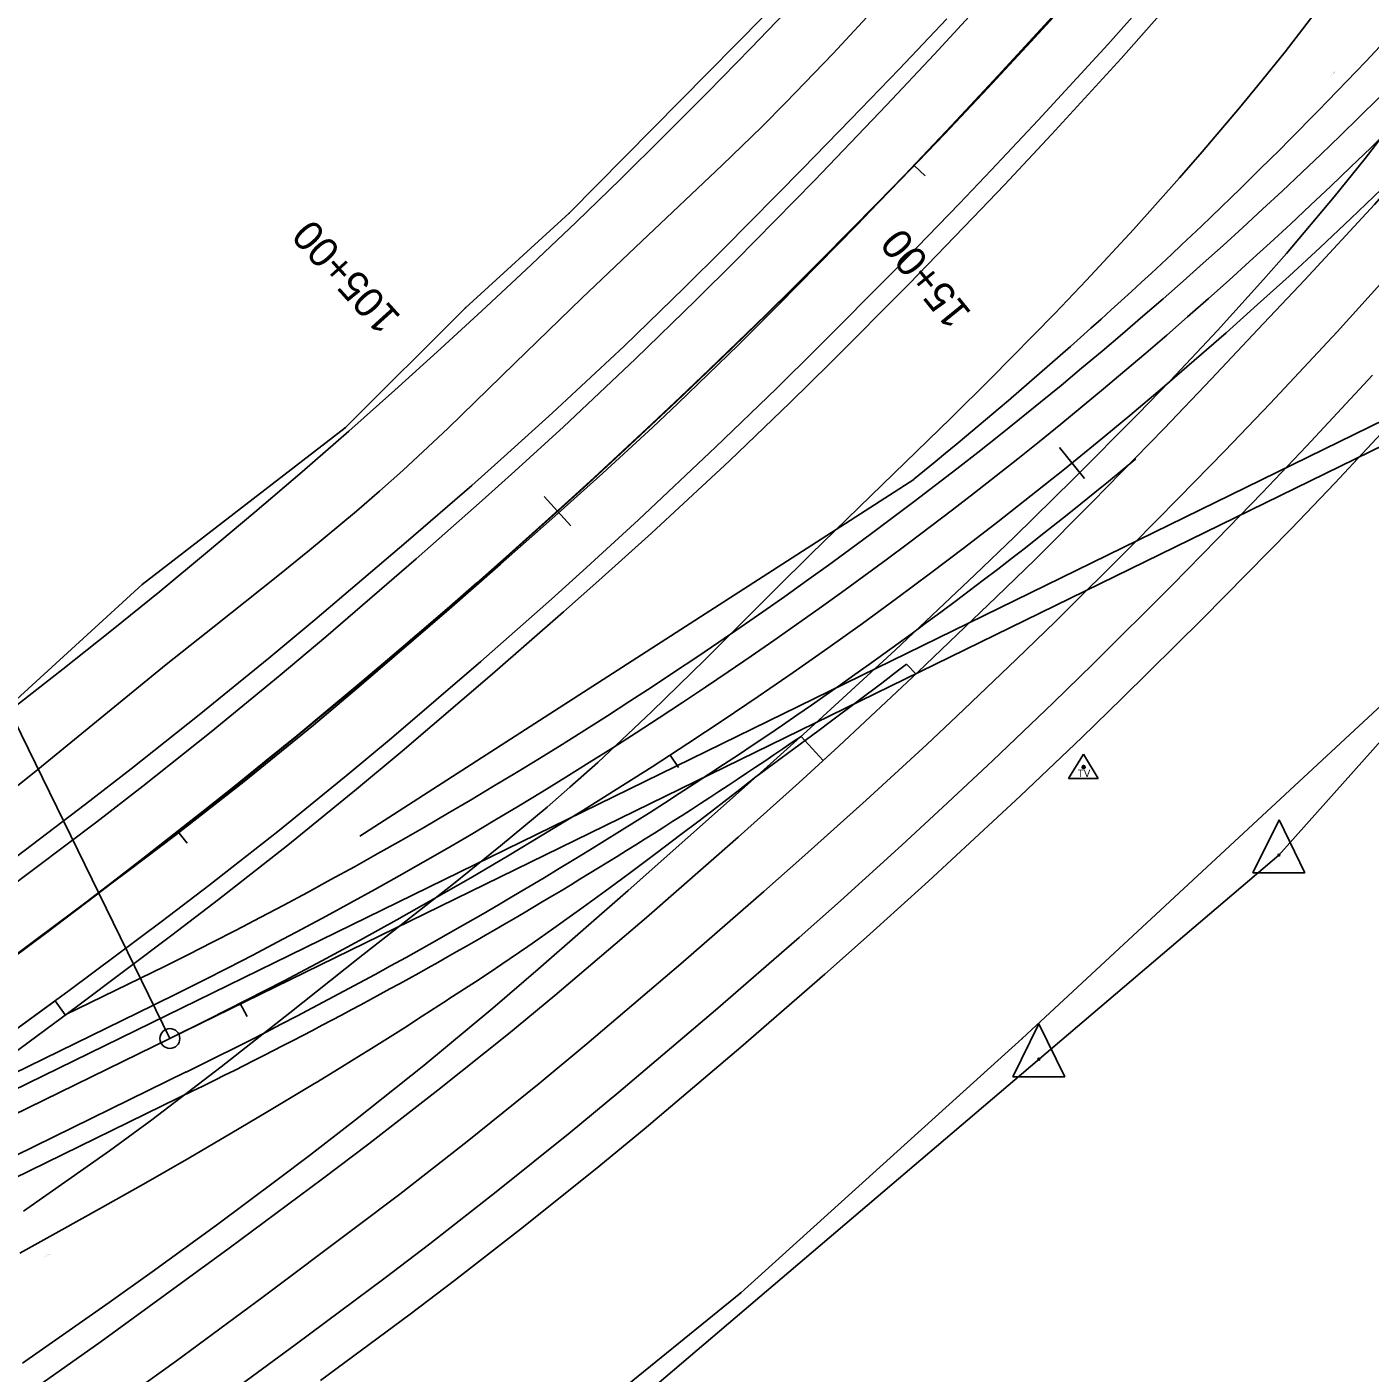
# Model space of a CAD drawing. Extents: x 1674300 to 1677920, y 225056 to 231852.
# Drawn here: x 1676793.2 to 1677063.6, y 227740.3 to 228011.3 of the extents above; entities that cross this region are included whole.
import ezdxf

# ---------------------------------------------------------------- set-up
doc = ezdxf.new("R2010")
doc.units = 0
for name, color, linetype in [('R_Annotation', 7, 'Continuous'), ('R_Horz Alg', 7, 'Continuous'), ('R_Horz Alg Annot', 7, 'Continuous'), ('R_Proposed Const Limits_Fill', 7, 'Continuous'), ('R_Proposed Road_Lane', 7, 'Continuous'), ('R_Proposed Road_Shoulder', 7, 'Continuous'), ('S_DITCHLINE', 7, 'Continuous'), ('S_EDGE_PAVEMENT', 7, 'Continuous'), ('S_EXIST_ROW', 7, 'Continuous'), ('S_EXISTING_ALIGNMENT', 7, 'Continuous'), ('S_FIBER_OPTIC_CABLE', 7, 'Continuous'), ('S_PAVEMENT_CROWN', 7, 'Continuous'), ('S_SECONDARY_CTL', 7, 'Continuous'), ('S_SHOULDER', 7, 'Continuous'), ('S_UTL_PT_SYM', 7, 'Continuous')]:
    doc.layers.add(name, color=color, linetype=linetype)

msp = doc.modelspace()

# ---------------------------------------------------------------- linework, layer by layer
at = {"layer": 'R_Horz Alg'}
msp.add_line((1676566.75, 227682.84), (1676822.03, 227807.69), dxfattribs=at)
for centre, radius, end in [((1675928.16, 228988.54), 1449, 0.80558), ((1676402.48, 228665.51), 954.93, 328.88259)]:
    msp.add_arc(centre, radius, 296.0624, end, dxfattribs=at)
at = {"layer": 'R_Horz Alg Annot'}
for p, q in [((1676564.78, 227686.88), (1677389.93, 228090.45)), ((1676822.03, 227807.69), (1677074.66, 227931.25))]:
    msp.add_line(p, q, dxfattribs=at)
for points in [[(1676974.02, 227981.32), (1676971.86, 227983.41)], [(1677001.08, 227926.63), (1677006.11, 227920.42)], [(1676822.03, 227807.69), (1676769.3, 227915.48)], [(1676897.38, 227916.79), (1676902.74, 227910.86)], [(1676924.38, 227862.24), (1676922.74, 227864.75)], [(1676825.49, 227847.01), (1676823.64, 227849.36)], [(1676837.55, 227812.09), (1676836.19, 227814.76)]]:
    msp.add_lwpolyline(points, dxfattribs=at)
msp.add_circle((1676822.03, 227807.69), 2, dxfattribs=at)
at = {"layer": 'R_Proposed Const Limits_Fill'}
msp.add_line((1676970.31, 227883.06), (1676972.23, 227881.05), dxfattribs=at)
for points in [[(1676860.25, 227848.42), (1676971.76, 227920.24)], [(1676791.82, 227764.49), (1676799.7, 227768.86), (1676808.45, 227773.71), (1676817.16, 227778.65), (1676825.85, 227783.62), (1676834.5, 227788.69), (1676841.39, 227792.77), (1676843.11, 227793.8), (1676851.16, 227798.64), (1676851.72, 227798.97), (1676856.62, 227801.97), (1676860.5, 227804.37), (1676862.05, 227805.32), (1676867.46, 227808.7), (1676869.23, 227809.82), (1676872.83, 227812.15), (1676877.85, 227815.42), (1676878.17, 227815.64), (1676883.52, 227819.1), (1676886.46, 227821.03), (1676888.82, 227822.64), (1676894.08, 227826.23), (1676894.95, 227826.82), (1676899.3, 227829.88), (1676903.32, 227832.77), (1676904.47, 227833.6), (1676909.62, 227837.34), (1676911.62, 227838.8), (1676914.76, 227841.08), (1676919.83, 227844.91), (1676919.84, 227844.92), (1676924.9, 227848.75), (1676928.01, 227851.1), (1676929.95, 227852.58), (1676934.98, 227856.45), (1676936.12, 227857.33), (1676939.99, 227860.33), (1676944.26, 227863.49), (1676945.07, 227864.09), (1676950.14, 227867.87), (1676952.43, 227869.57), (1676955.21, 227871.64), (1676960.26, 227875.42), (1676960.59, 227875.66), (1676965.3, 227879.22), (1676968.69, 227881.82), (1676970.31, 227883.06)]]:
    msp.add_lwpolyline(points, dxfattribs=at)
msp.add_arc((1676364.65, 228668.23), 963.36, 309.06481, 319.55161, dxfattribs=at)
at = {"layer": 'R_Proposed Road_Lane'}
for p, q in [((1676748.93, 227780.28), (1676818.73, 227814.42)), ((1676570.05, 227676.1), (1676825.32, 227800.95))]:
    msp.add_line(p, q, dxfattribs=at)
for points in [[(1676953.5, 227863.64), (1676956.64, 227866.52), (1676972.6, 227881.4), (1676988.37, 227896.5), (1676996.17, 227904.12), (1677007.75, 227915.68), (1677022.13, 227930.45), (1677031.62, 227940.39), (1677041.04, 227950.41), (1677050.47, 227960.42), (1677064.47, 227975.57), (1677071.28, 227983.29), (1677077.87, 227991.2), (1677081.05, 227995.24), (1677086, 228001.89), (1677089.18, 228006.41), (1677095.28, 228015.66), (1677102.54, 228027.13)], [(1676602.96, 227693.74), (1676603.67, 227694.1), (1676620.43, 227702.92), (1676631.53, 227708.93), (1676638.9, 227713), (1676653.56, 227721.26), (1676669.8, 227730.7), (1676680.55, 227737.1), (1676691.25, 227743.62), (1676701.94, 227750.13), (1676720.46, 227761.74), (1676729.67, 227767.63), (1676743.4, 227776.59), (1676757.03, 227785.7), (1676763.8, 227790.32), (1676776.54, 227799.18), (1676784.98, 227805.17), (1676798.91, 227815.26)]]:
    msp.add_lwpolyline(points, dxfattribs=at)
for radius, end in [(947.43, 317.63818), (962.43, 309.63823)]:
    msp.add_arc((1676402.48, 228665.51), radius, 296.0624, end, dxfattribs=at)
at = {"layer": 'R_Proposed Road_Shoulder'}
for p, q in [((1676949.06, 227868.5), (1676953.5, 227863.64)), ((1676800.97, 227812.42), (1676816.09, 227819.81)), ((1676800.97, 227812.42), (1676798.91, 227815.26)), ((1676571.81, 227672.51), (1676827.08, 227797.35))]:
    msp.add_line(p, q, dxfattribs=at)
for radius, end in [(941.43, 317.05629), (966.43, 304.44158)]:
    msp.add_arc((1676402.48, 228665.51), radius, 296.0624, end, dxfattribs=at)
at = {"layer": 'S_DITCHLINE'}
for points in [[(1676781.31, 227850.55), (1676794.72, 227861.22), (1676812.4, 227875.73), (1676821.28, 227882.95), (1676830.91, 227890.62), (1676843.77, 227900.81), (1676850.15, 227905.95), (1676859.6, 227913.82), (1676864.24, 227917.84), (1676868.89, 227922.01), (1676878.02, 227930.53), (1676891.46, 227943.62), (1676904.91, 227956.71), (1676917.04, 227968.18), (1676933.22, 227983.46), (1676941.18, 227991.22), (1676946.01, 227996.08), (1676955.51, 228005.96), (1676964.85, 228016)], [(1676792.57, 227772.92), (1676809.85, 227785.11), (1676818.4, 227791.33), (1676832.36, 227801.97), (1676846.14, 227812.86), (1676859.92, 227823.76), (1676879.09, 227838.84), (1676888.6, 227846.47), (1676897.95, 227854.27), (1676902.55, 227858.26), (1676908.13, 227863.25), (1676919.05, 227873.5), (1676929.77, 227883.98), (1676943.92, 227898.11), (1676951.02, 227905.16), (1676963.08, 227916.92), (1676979.21, 227932.56), (1676987.2, 227940.45), (1677000.17, 227953.65), (1677006.55, 227960.36), (1677015.99, 227970.55), (1677025.23, 227980.9), (1677029.79, 227986.13), (1677037.31, 227995.01), (1677041.02, 227999.5), (1677046.49, 228006.3), (1677054.51, 228016.66)]]:
    msp.add_lwpolyline(points, dxfattribs=at)
at = {"layer": 'S_EDGE_PAVEMENT'}
for points in [[(1676784.98, 227805.17), (1676801.74, 227817.32), (1676820.56, 227831.36), (1676829.88, 227838.49), (1676843.73, 227849.37), (1676857.53, 227860.58), (1676866.63, 227868.17), (1676884.63, 227883.6), (1676898.83, 227896.15), (1676905.87, 227902.49), (1676916.35, 227912.09), (1676931.88, 227926.7), (1676944.11, 227938.52), (1676952.18, 227946.48), (1676968.16, 227962.57), (1676980.99, 227975.79), (1676987.34, 227982.45), (1676996.8, 227992.52), (1677010.8, 228007.79), (1677018.43, 228016.32)], [(1676788.62, 227837.24), (1676807.31, 227851.32), (1676816.56, 227858.49), (1676830.31, 227869.4), (1676844.24, 227880.82), (1676853.44, 227888.54), (1676871.63, 227904.22), (1676884.89, 227915.95), (1676891.46, 227921.87), (1676901.25, 227930.84), (1676915.74, 227944.48), (1676927.9, 227956.29), (1676935.92, 227964.26), (1676951.76, 227980.38), (1676966.27, 227995.53), (1676975.83, 228005.73), (1676985.29, 228016.04)], [(1676788.32, 227732.7), (1676795.19, 227737.48), (1676808.2, 227746.7), (1676821.09, 227756.09), (1676833.98, 227765.47), (1676852.77, 227779.44), (1676862.1, 227786.51), (1676875.97, 227797.27), (1676890.15, 227808.64), (1676899.5, 227816.34), (1676917.98, 227832.01), (1676936.44, 227848.2), (1676948.6, 227859.15), (1676956.64, 227866.52), (1676972.6, 227881.4), (1676988.37, 227896.5), (1676996.17, 227904.12), (1677007.75, 227915.68), (1677022.13, 227930.45), (1677031.62, 227940.39), (1677041.04, 227950.41), (1677050.47, 227960.42), (1677064.47, 227975.57)], [(1676829.81, 227733.24), (1676847.27, 227746), (1676865.35, 227759.54), (1676874.33, 227766.39), (1676887.68, 227776.81), (1676902.58, 227788.79), (1676912.41, 227796.9), (1676922.15, 227805.14), (1676931.88, 227813.37), (1676948.66, 227827.99), (1676956.98, 227835.38), (1676969.35, 227846.58), (1676978.52, 227855.1), (1676987.68, 227863.63), (1676999.83, 227875.26), (1677007.86, 227883.09), (1677023.76, 227898.92), (1677032.82, 227908.22), (1677041.88, 227917.51), (1677050.82, 227926.92), (1677064.06, 227941.19)]]:
    msp.add_lwpolyline(points, dxfattribs=at)
at = {"layer": 'S_EXIST_ROW'}
for p, q in [((1677045.25, 227844.61), (1677191.98, 228009.21)), ((1677045.27, 227851.7), (1677039.98, 227841.06)), ((1677045.27, 227851.7), (1677050.5, 227841.06)), ((1676877.29, 227701.73), (1677045.25, 227844.61)), ((1677045.25, 227844.61), (1677045.25, 227844.61)), ((1677039.98, 227841.06), (1677050.5, 227841.06)), ((1676996.96, 227810.61), (1676991.67, 227799.97)), ((1676996.96, 227810.61), (1677002.19, 227799.97)), ((1676996.94, 227803.52), (1676996.94, 227803.52)), ((1676991.67, 227799.97), (1677002.19, 227799.97))]:
    msp.add_line(p, q, dxfattribs=at)
for centre, radius in [((1677045.25, 227844.61), 0.18), ((1677045.25, 227844.61), 0.09), ((1676996.94, 227803.52), 0.18), ((1676996.94, 227803.52), 0.09)]:
    msp.add_circle(centre, radius, dxfattribs=at)
msp.add_arc((1675926.71, 228989.39), 1410.53, 295.94359, 0.85682, dxfattribs=at)
at = {"layer": 'S_EXISTING_ALIGNMENT'}
for start, end in [(315.98862, 345.81316), (295.94359, 315.98862)]:
    msp.add_arc((1675926.71, 228989.39), 1450.53, start, end, dxfattribs=at)
at = {"layer": 'S_FIBER_OPTIC_CABLE'}
for p, q in [((1676902.41, 227973.8), (1676941.57, 228013.45)), ((1676881.55, 227954.79), (1676902.41, 227973.8)), ((1676857.28, 227930.62), (1676881.55, 227954.79)), ((1676816.44, 227899.08), (1676857.28, 227930.62)), ((1676773.26, 227859.62), (1676816.44, 227899.08)), ((1676993.59, 227807.69), (1677078.18, 227886.24)), ((1676936.92, 227756.51), (1676993.59, 227807.69)), ((1676864.37, 227697.61), (1676936.92, 227756.51))]:
    msp.add_line(p, q, dxfattribs=at)
at = {"layer": 'S_PAVEMENT_CROWN'}
for points in [[(1676778.53, 227815.24), (1676795.14, 227827.6), (1676813.86, 227841.57), (1676823.17, 227848.63), (1676836.98, 227859.39), (1676850.91, 227870.74), (1676860.08, 227878.46), (1676878.25, 227894.1), (1676888.59, 227903.18), (1676898.92, 227912.26), (1676909.14, 227921.46), (1676919.24, 227930.77), (1676924.24, 227935.49), (1676936.46, 227947.31), (1676944.49, 227955.3), (1676960.36, 227971.5), (1676969.86, 227981.46), (1676979.36, 227991.43), (1676988.75, 228001.5), (1677002.67, 228016.75)], [(1676814.6, 227736.48), (1676823.36, 227742.84), (1676840.79, 227755.69), (1676859.15, 227769.42), (1676868.28, 227776.36), (1676881.84, 227786.93), (1676896.36, 227798.66), (1676905.93, 227806.61), (1676924.9, 227822.74), (1676941.58, 227837.25), (1676949.86, 227844.57), (1676962.19, 227855.65), (1676974.4, 227866.87), (1676980.44, 227872.54), (1676992.37, 227883.95), (1677000.25, 227891.63), (1677015.87, 227907.15), (1677025.12, 227916.55), (1677034.37, 227925.96), (1677043.5, 227935.48), (1677056.99, 227949.95), (1677068.17, 227962.37)]]:
    msp.add_lwpolyline(points, dxfattribs=at)
at = {"layer": 'S_SECONDARY_CTL'}
for p, q in [((1677005.94, 227864.94), (1677002.93, 227859.99)), ((1677005.94, 227864.94), (1677008.89, 227859.99)), ((1677002.93, 227859.99), (1677008.89, 227859.99))]:
    msp.add_line(p, q, dxfattribs=at)
for radius in [0.311, 0.183, 0.103]:
    msp.add_circle((1677005.94, 227862.33), radius, dxfattribs=at)
at = {"layer": 'S_SHOULDER'}
for points in [[(1676786.46, 227840.75), (1676805.03, 227854.85), (1676814.23, 227862), (1676827.93, 227872.86), (1676841.95, 227884.27), (1676851.23, 227891.96), (1676869.6, 227907.56), (1676882.78, 227919.03), (1676889.32, 227924.83), (1676899.05, 227933.62), (1676913.43, 227947.02), (1676925.55, 227958.78), (1676933.54, 227966.71), (1676949.36, 227982.73), (1676959.07, 227992.77), (1676968.79, 228002.8), (1676978.38, 228012.96)], [(1676786.9, 227802.03), (1676803.5, 227814.28), (1676822.41, 227828.48), (1676831.8, 227835.67), (1676845.75, 227846.62), (1676859.62, 227857.9), (1676868.77, 227865.53), (1676886.9, 227881.02), (1676901.24, 227893.54), (1676908.36, 227899.86), (1676918.96, 227909.41), (1676934.66, 227923.98), (1676946.86, 227935.69), (1676954.9, 227943.6), (1676970.81, 227959.61), (1676983.65, 227972.85), (1676990.02, 227979.53), (1676999.48, 227989.62), (1677013.47, 228004.94), (1677021.15, 228013.58)], [(1676792.33, 227742.34), (1676809.79, 227754.55), (1676818.46, 227760.73), (1676831.39, 227770.12), (1676843.92, 227779.42), (1676850.14, 227784.14), (1676859.4, 227791.3), (1676873.12, 227802.25), (1676887.01, 227813.8), (1676896.16, 227821.63), (1676914.3, 227837.49), (1676926.31, 227848.15), (1676938.32, 227858.82), (1676950.25, 227869.58), (1676967.99, 227885.88), (1676984.05, 227901.03), (1676992, 227908.68), (1677003.82, 227920.28), (1677016.89, 227933.41), (1677023.33, 227940.06), (1677032.86, 227950.17), (1677042.18, 227960.47), (1677046.75, 227965.69), (1677056.34, 227977.09), (1677062.58, 227984.81), (1677066.67, 227990.02)], [(1676852.37, 227738.82), (1676870.37, 227752.23), (1676879.32, 227759.01), (1676892.63, 227769.3), (1676907.6, 227781.29), (1676917.46, 227789.41), (1676927.22, 227797.68), (1676936.97, 227805.94), (1676953.88, 227820.66), (1676962.26, 227828.1), (1676974.74, 227839.37), (1676983.99, 227847.94), (1676993.24, 227856.51), (1677005.57, 227868.27), (1677013.73, 227876.18), (1677029.88, 227892.15), (1677038.8, 227901.22), (1677047.73, 227910.29), (1677056.53, 227919.47), (1677069.55, 227933.42)]]:
    msp.add_lwpolyline(points, dxfattribs=at)
at = {"layer": 'S_UTL_PT_SYM'}
for points in [[(1676902.41, 227973.8), (1676902.41, 227973.85), (1676902.41, 227973.8), (1676902.36, 227973.8), (1676902.41, 227973.8), (1676902.41, 227973.75), (1676902.41, 227973.8), (1676902.46, 227973.8)], [(1676881.55, 227954.79), (1676881.55, 227954.84), (1676881.55, 227954.79), (1676881.5, 227954.79), (1676881.55, 227954.79), (1676881.55, 227954.74), (1676881.55, 227954.79), (1676881.6, 227954.79)], [(1676857.28, 227930.62), (1676857.28, 227930.67), (1676857.28, 227930.62), (1676857.23, 227930.62), (1676857.28, 227930.62), (1676857.28, 227930.57), (1676857.28, 227930.62), (1676857.33, 227930.62)], [(1676816.44, 227899.08), (1676816.44, 227899.13), (1676816.44, 227899.08), (1676816.39, 227899.08), (1676816.44, 227899.08), (1676816.44, 227899.03), (1676816.44, 227899.08), (1676816.49, 227899.08)], [(1676993.59, 227807.69), (1676993.59, 227807.74), (1676993.59, 227807.69), (1676993.54, 227807.69), (1676993.59, 227807.69), (1676993.59, 227807.64), (1676993.59, 227807.69), (1676993.64, 227807.69)], [(1676936.92, 227756.51), (1676936.92, 227756.56), (1676936.92, 227756.51), (1676936.87, 227756.51), (1676936.92, 227756.51), (1676936.92, 227756.46), (1676936.92, 227756.51), (1676936.97, 227756.51)]]:
    msp.add_lwpolyline(points, dxfattribs=at)

# ---------------------------------------------------------------- texts
at = {"layer": 'R_Annotation'}
for rotation, p in [(46.0568, (1677055.72, 228001.35)), (28.9977, (1676796.75, 227763.66))]:
    msp.add_text('CONST. LIMITS', height=0.12, rotation=rotation, dxfattribs=at).set_placement(p)
at = {"layer": 'R_Horz Alg Annot'}
for s, rotation, p in [('105+00', 132.1242, (1676868.75, 227952.92)), ('15+00', 129.0123, (1676983.54, 227953.72))]:
    msp.add_text(s, height=6, rotation=rotation, dxfattribs=at).set_placement(p)
at = {"layer": 'S_SECONDARY_CTL'}
msp.add_text('TV', height=1.5, rotation=360, dxfattribs=at).set_placement((1677004.74, 227860.32))

doc.saveas('drawing.dxf')
